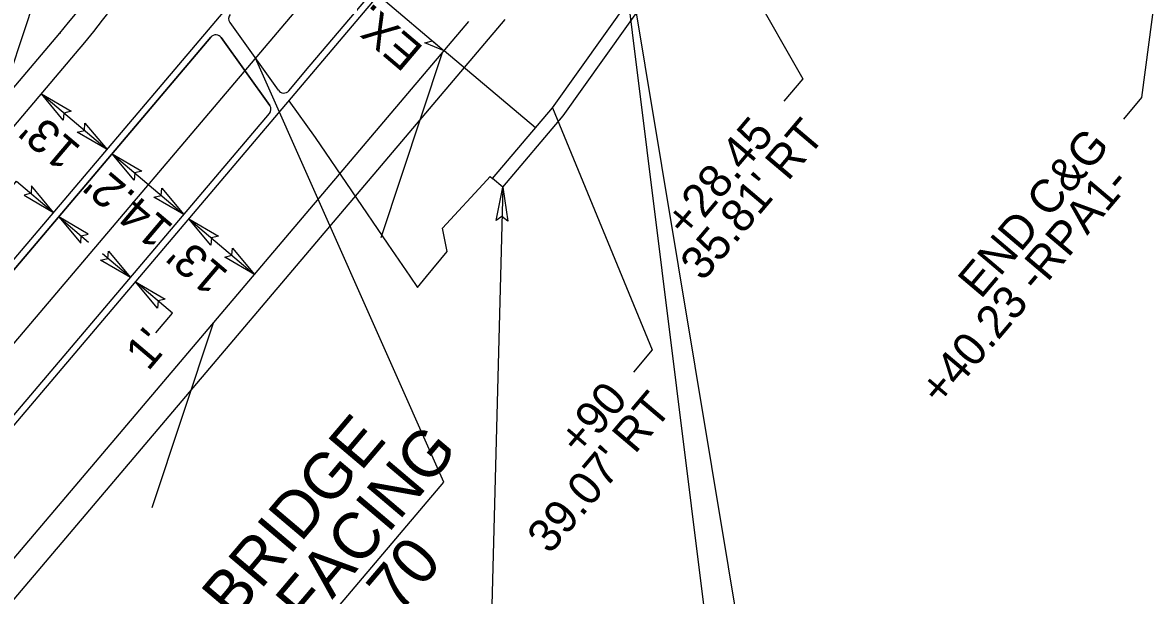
# Model space of a CAD drawing. Extents: x 1761082 to 1764358, y 421907 to 425434.
# Drawn here: x 1762595.2 to 1762765.1, y 423406.5 to 423493.1 of the extents above; entities that cross this region are included whole.
import ezdxf

# ---------------------------------------------------------------- set-up
doc = ezdxf.new("R2010")
doc.units = 0
for name, color, linetype in [('MARK LEFT TURN ARROW CELL', 7, 'Continuous'), ('MARK STRAIGHT RIGHT ARROW CELL', 7, 'Continuous'), ('MARK UTURN ARROW CELL', 7, 'Continuous'), ('Prop Mkg 3ft Min Skp 3ft Wide White', 7, 'Continuous'), ('Prop Mkg Min Skp 6ft Yellow', 7, 'Continuous'), ('Prop Mkg Skp Wht', 7, 'Continuous'), ('Prop Mkg Solid White Diagonals', 7, 'Continuous'), ('Prop Mkg Solid White Lane Line', 7, 'Continuous'), ('Prop Mkg Solid White Wide Lane Line', 7, 'Continuous'), ('Prop Mkg Solid Yel Skip LT', 7, 'Continuous'), ('Prop Mkg Solid Yel Skip RT', 7, 'Continuous'), ('Prop Mkg Solid Yellow Lane Line', 7, 'Continuous'), ('Scratch_Level_0', 7, 'Continuous'), ('Scratch_Level_1', 7, 'Continuous'), ('Scratch_Level_5', 7, 'Continuous'), ('Text', 7, 'Continuous')]:
    doc.layers.add(name, color=color, linetype=linetype)

msp = doc.modelspace()

# ---------------------------------------------------------------- linework, layer by layer
at = {"layer": 'MARK LEFT TURN ARROW CELL'}
for p, q in [((1762676.87, 423478.99), (1762699.58, 423510.9)), ((1762667.77, 423468.24), (1762676.87, 423478.99)), ((1762667.77, 423468.24), (1762666.24, 423469.53))]:
    msp.add_line(p, q, dxfattribs=at)
at = {"layer": 'MARK STRAIGHT RIGHT ARROW CELL'}
msp.add_line((1761294.53, 421910.78), (1762672.97, 423537.92), dxfattribs=at)
at = {"layer": 'MARK UTURN ARROW CELL'}
for points in [[(1762680.61, 423545.38), (1762700.7, 423384.1), (1762621.03, 423290.05)], [(1762572.31, 423321.5), (1762658.86, 423423.66), (1762630.42, 423487.69)]]:
    msp.add_lwpolyline(points, dxfattribs=at)
at = {"layer": 'Prop Mkg 3ft Min Skp 3ft Wide White'}
msp.add_line((1761294.53, 421910.78), (1762672.97, 423537.92), dxfattribs=at)
at = {"layer": 'Prop Mkg Skp Wht'}
for p, q in [((1762675.29, 423480.21), (1762697.66, 423511.66)), ((1762666.24, 423469.53), (1762675.29, 423480.21)), ((1762658.69, 423462), (1762665.34, 423469.25)), ((1762665.34, 423469.25), (1762665.87, 423469.85)), ((1762665.87, 423469.85), (1762666.24, 423469.53)), ((1762659.38, 423458.5), (1762658.69, 423462)), ((1762656.27, 423454.72), (1762659.38, 423458.5)), ((1762653.73, 423454.77), (1762654.91, 423453.06)), ((1762654.91, 423453.06), (1762656.27, 423454.72))]:
    msp.add_line(p, q, dxfattribs=at)
msp.add_lwpolyline([(1762635.47, 423481.27), (1762639.44, 423475.71), (1762650.42, 423459.6), (1762653.73, 423454.77)], dxfattribs=at)
at = {"layer": 'Prop Mkg Solid White Diagonals'}
for p, q in [((1762638.54, 423486.44), (1762664.19, 423516.72)), ((1762626.56, 423493.1), (1762633.87, 423482.86)), ((1762623.68, 423490.87), (1762480.79, 423322.2)), ((1762632.57, 423480.56), (1762625.26, 423490.81)), ((1762635.45, 423482.79), (1762638.54, 423486.44)), ((1762489.87, 423310.95), (1762632.52, 423479.34))]:
    msp.add_line(p, q, dxfattribs=at)
for centre, start, end in [((1762624.45, 423490.23), 35.5224, 139.7301), ((1762634.69, 423483.44), 215.5224, 319.7301), ((1762631.76, 423479.98), 319.7301, 35.5224)]:
    msp.add_arc(centre, 1, start, end, dxfattribs=at)
at = {"layer": 'Prop Mkg Solid White Lane Line'}
for p, q in [((1762638.54, 423486.44), (1762664.19, 423516.72)), ((1762626.56, 423493.1), (1762633.87, 423482.86)), ((1762480.79, 423322.2), (1762623.68, 423490.87)), ((1762635.45, 423482.79), (1762638.54, 423486.44))]:
    msp.add_line(p, q, dxfattribs=at)
for centre, start, end in [((1762627.37, 423493.68), 139.7301, 215.5224), ((1762624.45, 423490.23), 35.5224, 139.7301), ((1762634.69, 423483.44), 215.5224, 319.7301)]:
    msp.add_arc(centre, 1, start, end, dxfattribs=at)
at = {"layer": 'Prop Mkg Solid White Wide Lane Line'}
for p, q in [((1762574.37, 423382.84), (1762668.14, 423493.53)), ((1762508.22, 423382.12), (1762600.89, 423491.5))]:
    msp.add_line(p, q, dxfattribs=at)
msp.add_circle((1762600.89, 423491.5), 0.0417, dxfattribs=at)
msp.add_circle((1762600.89, 423491.5), 0.0417, dxfattribs=at)
msp.add_arc((1762501.69, 423575.53), 130, 319.7301, 348.5699, dxfattribs=at)
at = {"layer": 'Prop Mkg Solid Yel Skip RT'}
for p, q in [((1762598.08, 423482.31), (1762608, 423473.91)), ((1762608.76, 423473.26), (1762619.6, 423464.08)), ((1762600.7, 423463.75), (1762605.21, 423459.92)), ((1762620.36, 423463.43), (1762630.28, 423455.03)), ((1762611.54, 423454.57), (1762607.32, 423458.14))]:
    msp.add_line(p, q, dxfattribs=at)
for points in [[(1762774.26, 423557.48), (1762764.26, 423481.75), (1762761.5, 423478.49)], [(1762697.66, 423511.66), (1762713.08, 423484.59), (1762710.24, 423481.23)], [(1762675.29, 423480.21), (1762690.33, 423443.63), (1762687.49, 423440.28)], [(1762591.84, 423466.16), (1762594.35, 423469.12), (1762599.94, 423464.39)], [(1762667.77, 423468.24), (1762666.05, 423403.09), (1762663.21, 423399.74)], [(1762615.37, 423446.22), (1762617.89, 423449.19), (1762612.3, 423453.92)]]:
    msp.add_lwpolyline(points, dxfattribs=at)
at = {"layer": 'Prop Mkg Solid Yellow Lane Line'}
for points in [[(1762601.4, 423478.34), (1762598.08, 423482.31), (1762602.58, 423479.68), (1762601.5, 423479.41)], [(1762604.67, 423477.87), (1762608, 423473.91), (1762603.5, 423476.53), (1762604.58, 423476.8)], [(1762612.09, 423469.29), (1762608.76, 423473.26), (1762613.26, 423470.63), (1762612.18, 423470.36)], [(1762595.48, 423467.02), (1762599.94, 423464.39), (1762596.61, 423468.4), (1762596.52, 423467.29)], [(1762616.27, 423468.05), (1762619.6, 423464.08), (1762615.09, 423466.7), (1762616.18, 423466.98)], [(1762666.75, 423463.16), (1762667.77, 423468.24), (1762668.54, 423463.09), (1762667.65, 423463.76)], [(1762605.16, 423461.12), (1762600.7, 423463.75), (1762604.03, 423459.74), (1762604.12, 423460.85)], [(1762623.68, 423459.46), (1762620.36, 423463.43), (1762624.86, 423460.81), (1762623.78, 423460.54)], [(1762608.21, 423458.54), (1762611.54, 423454.57), (1762607.03, 423457.19), (1762608.12, 423457.46)], [(1762626.95, 423459), (1762630.28, 423455.03), (1762625.78, 423457.66), (1762626.86, 423457.93)], [(1762615.62, 423449.95), (1762612.3, 423453.92), (1762616.8, 423451.3), (1762615.72, 423451.02)]]:
    msp.add_lwpolyline(points, close=True, dxfattribs=at)
at = {"layer": 'Scratch_Level_0'}
for p, q in [((1762610.02, 423535.74), (1762588.62, 423471.14)), ((1762299.96, 423085.24), (1762664.95, 423516.07)), ((1762278.7, 423085.2), (1762626.96, 423496.29)), ((1762339.89, 423112.25), (1762662.64, 423493.23)), ((1762377.21, 423221.6), (1762603.25, 423488.41)), ((1762658.64, 423488.5), (1762649.37, 423460.56)), ((1762672.7, 423477.16), (1762658.92, 423488.84)), ((1762624.03, 423447.66), (1762614.79, 423419.78))]:
    msp.add_line(p, q, dxfattribs=at)
msp.add_arc((1762488.8, 423585.37), 150, 319.7301, 346.1144, dxfattribs=at)
at = {"layer": 'Scratch_Level_1'}
msp.add_line((1762508.22, 423382.12), (1762600.89, 423491.5), dxfattribs=at)
msp.add_lwpolyline([(1762679.14, 423547.37), (1762704.35, 423395.7), (1762650.35, 423331.96)], dxfattribs=at)
msp.add_circle((1762600.89, 423491.5), 0.0417, dxfattribs=at)
msp.add_circle((1762600.89, 423491.5), 0.0417, dxfattribs=at)
msp.add_arc((1762501.69, 423575.53), 130, 319.7301, 348.5699, dxfattribs=at)
at = {"layer": 'Scratch_Level_5'}
msp.add_line((1762649, 423497.24), (1762658.92, 423488.84), dxfattribs=at)
msp.add_lwpolyline([(1762658.92, 423488.84), (1762655.98, 423490.02), (1762657.16, 423490.33)], close=True, dxfattribs=at)
at = {"layer": 'Text'}
for p, q in [((1762625.26, 423490.81), (1762632.57, 423480.56)), ((1762489.87, 423310.95), (1762632.52, 423479.34))]:
    msp.add_line(p, q, dxfattribs=at)
msp.add_arc((1762631.76, 423479.98), 1, 319.7301, 35.5224, dxfattribs=at)

# ---------------------------------------------------------------- texts
at = {"layer": 'MARK UTURN ARROW CELL'}
for s, p in [('END EXISTING BRIDGE', (1762582.78, 423350.13)), ('BEGIN MILLING/RESURFACING', (1762570.73, 423321.7)), ('-L- Sta. 30+66.70', (1762611.88, 423356.09))]:
    msp.add_text(s, height=7, rotation=49.7301, dxfattribs=at).set_placement(p)
at = {"layer": 'Prop Mkg Min Skp 6ft Yellow'}
msp.add_text('EX.', height=5, rotation=139.7301, dxfattribs=at).set_placement((1762655.99, 423489.26))
at = {"layer": 'Prop Mkg Solid Yel Skip LT'}
for s, rotation, p in [("35.81' RT", 49.7301, (1762697.99, 423453.84)), ("13'", 139.7301, (1762604.28, 423474.18)), ('+28.45', 49.7301, (1762695.61, 423460.33)), ('END C&G', 49.7301, (1762739.96, 423451.17)), ("14.2'", 139.7301, (1762618.26, 423462.33)), ('+40.23 -RPA1-', 49.7301, (1762734.04, 423434.9)), ("13'", 139.7301, (1762626.56, 423455.31)), ("1'", 49.7301, (1762614.21, 423440.29)), ('+90', 49.7301, (1762679.53, 423427.39)), ("39.07' RT", 49.7301, (1762674.87, 423412.6))]:
    msp.add_text(s, height=5, rotation=rotation, dxfattribs=at).set_placement(p)

doc.saveas('drawing.dxf')
